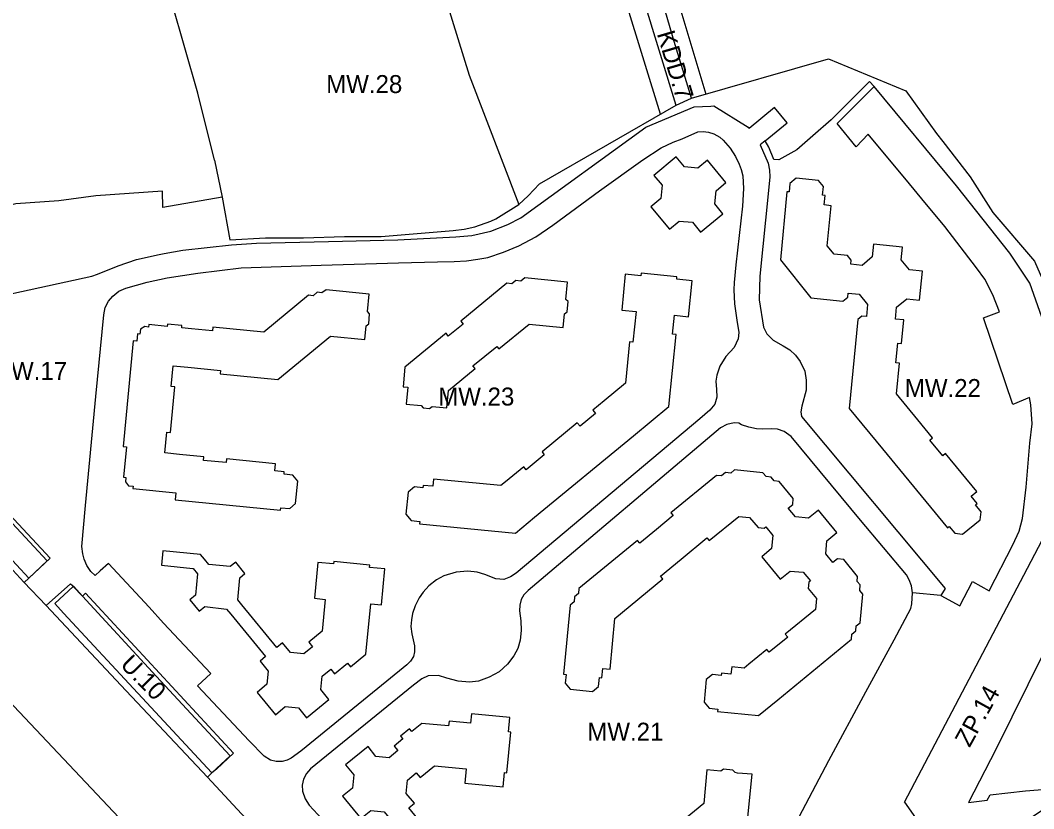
# Model space of a CAD drawing. Extents: x 7426178 to 7427732, y 5548847 to 5550287.
# Drawn here: x 7426699.7 to 7426953.6, y 5549707.1 to 5549904.6 of the extents above; entities that cross this region are included whole.
import ezdxf

# ---------------------------------------------------------------- set-up
doc = ezdxf.new("R2010")
doc.units = 0
for name, color, linetype in [('linie_rozgraniczajace', 7, 'Continuous'), ('linie_zabudowy_nieprzekraczalne', 7, 'Continuous'), ('linie_zabudowy_obowiazujace', 7, 'Continuous'), ('oznaczenia_przeznaczen', 7, 'Continuous')]:
    doc.layers.add(name, color=color, linetype=linetype)

msp = doc.modelspace()

# ---------------------------------------------------------------- linework, layer by layer
at = {"layer": 'linie_rozgraniczajace'}
for p, q in [((7426867.89, 5549885.09), (7426902.2, 5549894.9)), ((7426886.29, 5549874.39), (7426885.09, 5549873.37)), ((7426748.35, 5549869.5), (7426750.28, 5549860.25)), ((7426794.47, 5549843.8), (7426804.23, 5549844.06)), ((7426700.65, 5549763.84), (7426700.65, 5549763.84)), ((7426706.19, 5549757.95), (7426700.65, 5549763.84)), ((7426930.31, 5549760.48), (7426923.22, 5549761.13))]:
    msp.add_line(p, q, dxfattribs=at)
for points in [[(7426376.27, 5550136.98), (7426418.26, 5550074.28), (7426423.32, 5550066.18), (7426432.5, 5550051.32), (7426442.7, 5550038.38), (7426480.49, 5549982.45), (7426537.39, 5549902.3), (7426546.67, 5549891.59), (7426553.32, 5549883.92), (7426562.25, 5549871.78), (7426591.41, 5549843), (7426644.02, 5549790.07), (7426768.78, 5549657.84), (7426806.41, 5549611.72)], [(7426832.18, 5549989.03), (7426839.49, 5549964.6), (7426845.83, 5549943.49), (7426851.15, 5549925.23), (7426855.77, 5549910), (7426863.95, 5549883.29)], [(7426790.09, 5549942.81), (7426797.59, 5549944.63), (7426799.94, 5549929.65), (7426806.51, 5549909.21), (7426812.16, 5549890.84), (7426824.57, 5549858.44)], [(7426748.35, 5549869.5), (7426744.18, 5549886.34), (7426737.69, 5549909.01), (7426736.68, 5549911.95), (7426722.25, 5549906.56), (7426716.61, 5549921.27)], [(7426867.89, 5549885.09), (7426863.5, 5549899.25), (7426859.57, 5549912.74)], [(7426902.2, 5549894.9), (7426921.51, 5549886.93)], [(7426913.6, 5549887.98), (7426912.46, 5549889.24), (7426902.87, 5549879.62), (7426898.28, 5549875.63), (7426894.22, 5549872.08), (7426889.75, 5549869.63), (7426888.43, 5549869.71), (7426887.24, 5549872.76), (7426886.29, 5549874.39), (7426891.83, 5549878.89), (7426888.65, 5549882.71), (7426882.29, 5549877.48)], [(7426885.09, 5549873.37), (7426887.08, 5549868.75), (7426887.37, 5549867.04), (7426887.43, 5549865.33), (7426887.16, 5549861.94), (7426884.93, 5549840.48), (7426884.78, 5549834.57), (7426885.92, 5549827.69), (7426886.73, 5549826.02), (7426888.32, 5549824.44), (7426890.85, 5549823.06), (7426892.47, 5549822.01), (7426893.88, 5549820.67), (7426895.05, 5549819.06), (7426896.22, 5549816.67), (7426896.56, 5549814.46), (7426896.55, 5549811.95), (7426895.49, 5549807.9), (7426895.21, 5549806.51), (7426895.43, 5549805.3), (7426931.35, 5549762.2), (7426930.31, 5549760.48), (7426935.02, 5549757.91), (7426938.23, 5549763.99), (7426942.44, 5549761.68), (7426948.32, 5549773.17), (7426949.91, 5549776.58), (7426950.73, 5549779.76), (7426951.69, 5549787.64), (7426952.58, 5549798.68), (7426953.14, 5549803.51), (7426952.83, 5549808.21), (7426952.48, 5549810.07), (7426948.34, 5549808.36), (7426940.95, 5549830.03), (7426945.03, 5549831.5), (7426943.34, 5549835.78), (7426941.36, 5549839.75), (7426939.25, 5549842.52), (7426931.29, 5549852.9), (7426925.53, 5549859.82), (7426922.44, 5549863.63), (7426912.09, 5549876.06), (7426909.06, 5549872.85), (7426904.34, 5549878.68), (7426913.6, 5549887.98)], [(7426921.19, 5549708.68), (7426951.11, 5549765.58), (7426956.6, 5549776.07), (7426959.16, 5549797.97), (7426961.99, 5549798.27), (7426962.58, 5549807), (7426960.6, 5549815.99), (7426952.6, 5549838.71), (7426947.62, 5549846.2), (7426934.23, 5549863.11), (7426913.6, 5549887.98)], [(7426824.57, 5549858.44), (7426826.91, 5549860.63), (7426829.76, 5549863.61), (7426864.02, 5549883.33), (7426867.89, 5549885.09)], [(7426921.51, 5549886.93), (7426929.22, 5549876.25), (7426930.78, 5549874.24), (7426937.63, 5549865.37), (7426943.32, 5549856.38), (7426953.79, 5549844.23), (7426959.19, 5549831.83), (7426963.61, 5549821.24), (7426965.71, 5549809.49), (7426966.05, 5549784.81), (7426964.49, 5549773.85), (7426962.7, 5549765.31), (7426980.6, 5549768.08), (7426985.31, 5549769.35)], [(7426735.78, 5549846.15), (7426740.47, 5549846.99), (7426752.63, 5549848.35), (7426758.87, 5549848.74), (7426776.96, 5549849.18), (7426794.32, 5549849.61), (7426808.86, 5549850.31), (7426812.83, 5549850.66), (7426817.56, 5549851.74), (7426821.87, 5549853.43), (7426825.07, 5549855.05), (7426856.4, 5549877.8), (7426868.55, 5549882.89), (7426872.7, 5549883.08)], [(7426872.7, 5549883.08), (7426873.48, 5549883.12), (7426882.06, 5549877.83), (7426882.29, 5549877.48)], [(7426855.62, 5549869.6), (7426860.24, 5549872.59), (7426863.25, 5549874.07), (7426865.49, 5549874.87), (7426869.42, 5549876.62), (7426870.76, 5549876.69), (7426872.09, 5549876.51), (7426873.46, 5549876.16), (7426874.91, 5549875.26), (7426875.78, 5549874.55), (7426877.51, 5549872.54), (7426878.87, 5549870.41), (7426879.82, 5549868.55), (7426880.32, 5549867.19)], [(7426828.88, 5549850.34), (7426833.1, 5549853.24), (7426844.78, 5549861.82), (7426855.62, 5549869.6)], [(7426880.32, 5549867.19), (7426880.73, 5549865.64), (7426880.87, 5549862.43), (7426880.63, 5549858.02), (7426878.97, 5549843.29), (7426878.54, 5549838.85), (7426878.47, 5549837.06)], [(7426750.28, 5549860.25), (7426735.44, 5549857.68), (7426735.34, 5549861.78), (7426718.63, 5549860.57), (7426709.36, 5549859.35), (7426698.65, 5549858.57), (7426685.11, 5549855.15), (7426672.58, 5549851.69), (7426632.66, 5549838.16)], [(7426750.28, 5549860.25), (7426752.23, 5549849.57), (7426761.14, 5549850.09), (7426770.65, 5549850.06), (7426780.93, 5549850.37), (7426790.15, 5549850.41), (7426808.15, 5549851.95), (7426810.9, 5549852.24), (7426813.62, 5549852.86), (7426817.58, 5549854.29), (7426818.86, 5549854.84), (7426824.57, 5549858.44)], [(7426816.83, 5549845.12), (7426820.73, 5549846.46), (7426824.57, 5549848.08), (7426828.88, 5549850.34)], [(7426644.29, 5549825.35), (7426656.53, 5549812.26), (7426666.12, 5549802), (7426671.29, 5549806.84), (7426667.68, 5549810.5), (7426669.3, 5549829.97), (7426717.68, 5549840.5), (7426719.08, 5549840.97), (7426724.23, 5549843.09), (7426728.86, 5549844.63), (7426734.53, 5549845.92), (7426735.78, 5549846.15)], [(7426720.63, 5549830.76), (7426721.02, 5549832.59), (7426721.79, 5549834.21), (7426722.9, 5549835.49), (7426724.41, 5549836.7), (7426726.15, 5549837.47), (7426731.5, 5549838.99), (7426736.49, 5549840.05), (7426744.18, 5549841.23), (7426755.05, 5549842.6), (7426775.11, 5549843.2), (7426794.47, 5549843.8)], [(7426804.23, 5549844.06), (7426808.44, 5549844.17), (7426811.48, 5549844.3), (7426814.37, 5549844.7), (7426816.83, 5549845.12)], [(7426878.47, 5549837.06), (7426878.63, 5549833.52), (7426879.2, 5549829.47), (7426879.72, 5549826.34), (7426879.56, 5549824.81), (7426878.53, 5549822.59), (7426876.42, 5549820.38), (7426874.92, 5549817.91), (7426874.22, 5549815.71), (7426873.93, 5549814.16), (7426874.14, 5549812.07), (7426874.16, 5549810.16), (7426873.69, 5549808.44), (7426872.46, 5549806.87), (7426869.93, 5549804.73), (7426823.97, 5549766.11), (7426822.55, 5549765.15), (7426820.81, 5549764.53), (7426818.88, 5549764.63), (7426816.07, 5549765.74), (7426814.18, 5549766.3), (7426811.79, 5549766.57), (7426808.94, 5549766.36), (7426805.85, 5549765.43), (7426803.94, 5549764.41), (7426802.06, 5549762.94), (7426800.6, 5549761.31), (7426799.62, 5549759.92), (7426798.66, 5549757.86), (7426798, 5549755.96), (7426797.74, 5549754.41), (7426797.55, 5549752.76), (7426797.79, 5549750.89), (7426798.47, 5549747.91), (7426798.49, 5549746.35), (7426798.18, 5549745.24), (7426797.47, 5549744), (7426796.57, 5549743.11), (7426791.57, 5549739.05), (7426769.99, 5549721.48), (7426767.59, 5549719.76), (7426766.54, 5549719.23), (7426765.36, 5549718.94), (7426763.82, 5549718.93), (7426762.37, 5549719.28), (7426760.83, 5549720.2), (7426757.03, 5549724.12), (7426744.14, 5549737.88)], [(7426718.47, 5549765.47), (7426717.37, 5549766.48), (7426716.41, 5549767.96), (7426715.7, 5549769.61), (7426715.37, 5549770.94), (7426715.12, 5549772.73), (7426716.1, 5549783.07), (7426718.66, 5549810.36), (7426720.63, 5549830.76)], [(7426671.29, 5549806.84), (7426672.03, 5549807.52), (7426707.23, 5549769.84), (7426701.88, 5549764.81), (7426700.72, 5549763.76), (7426700.65, 5549763.84), (7426688.57, 5549776.82), (7426666.12, 5549802)], [(7426893.27, 5549702.02), (7426902.25, 5549719.14), (7426911.55, 5549736.38), (7426918.58, 5549749.41), (7426922.77, 5549757.19), (7426923.06, 5549758.37), (7426923.22, 5549761.13), (7426922.94, 5549762.89), (7426922.41, 5549764.43), (7426921.68, 5549765.63), (7426910.19, 5549779.38), (7426892.82, 5549800.3), (7426891.03, 5549801.54), (7426889.37, 5549802.15), (7426887.85, 5549802.27), (7426885.67, 5549802.16), (7426884.13, 5549802.22), (7426882.22, 5549802.63), (7426880.37, 5549803.27), (7426879.72, 5549803.64), (7426878.53, 5549803.71), (7426876.72, 5549803.35), (7426875.12, 5549802.5), (7426826.9, 5549761.75), (7426825.88, 5549760.63), (7426825.17, 5549759.46), (7426824.84, 5549758.04), (7426824.8, 5549756.63), (7426825.08, 5549754.14), (7426825.18, 5549751.73), (7426824.93, 5549749.3), (7426824.34, 5549747.23), (7426823.37, 5549745.39), (7426821.72, 5549743.32), (7426819.65, 5549741.39), (7426817.16, 5549740.01), (7426814.49, 5549739.06), (7426812.21, 5549738.81), (7426809.39, 5549739.05), (7426806.54, 5549739.74), (7426804.45, 5549740.45), (7426801.93, 5549740.38), (7426800.31, 5549739.64), (7426798.21, 5549738.03), (7426772.44, 5549717.11), (7426771.4, 5549715.92), (7426770.7, 5549714.46), (7426770.35, 5549713), (7426770.4, 5549711.46), (7426771.05, 5549709.57), (7426772.11, 5549707.95), (7426785.12, 5549693.98)], [(7426735.6, 5549753.59), (7426732.04, 5549757.54), (7426721.78, 5549768.52), (7426719.73, 5549766.67), (7426718.47, 5549765.47)], [(7426960.1, 5549754.29), (7426944.05, 5549721.95), (7426937.2, 5549708.62), (7426941.9, 5549709.19), (7426942.64, 5549710.57), (7426951.51, 5549711.54), (7426958.87, 5549712.14), (7426996.53, 5549715.51), (7427002.21, 5549716.59), (7427004.76, 5549717.21), (7427010.19, 5549718.81), (7427041.49, 5549731.55), (7427083.98, 5549748.53), (7427093.57, 5549752.35), (7427093.82, 5549751.76), (7427128.13, 5549765.67)], [(7426706.19, 5549757.95), (7426712.33, 5549763.43), (7426713.11, 5549762.75), (7426715.35, 5549760.32), (7426716.05, 5549761.09), (7426753.15, 5549720.96), (7426748.85, 5549716.98), (7426747.71, 5549716.05), (7426746.58, 5549715.01)], [(7426810.33, 5549646.2), (7426800.44, 5549656.88), (7426791.22, 5549666.83), (7426763.7, 5549696.53), (7426746.59, 5549715), (7426724.9, 5549738.06), (7426706.19, 5549757.95)], [(7426744.14, 5549737.88), (7426747.48, 5549740.97), (7426735.6, 5549753.59)], [(7426921.19, 5549708.68), (7426923.92, 5549704.82), (7426932.51, 5549700.17), (7426935.18, 5549699.15), (7426937.7, 5549698.72), (7426940.53, 5549698.67), (7426942.25, 5549698.99), (7426944.97, 5549699.87), (7426946.33, 5549700.48), (7426947.4, 5549701.24), (7426955.49, 5549706.64), (7426958.19, 5549707.88), (7426961.05, 5549708.75), (7426963.27, 5549709.23), (7426965.77, 5549709.6), (7426974.88, 5549710.13), (7426996.27, 5549711.61), (7427000.22, 5549712.16), (7427006.34, 5549713.7), (7427091.63, 5549747.86), (7427113.84, 5549707.59), (7427113.65, 5549702.41), (7427125.67, 5549680.75), (7427127, 5549680.04)]]:
    msp.add_lwpolyline(points, dxfattribs=at)
at = {"layer": 'linie_zabudowy_nieprzekraczalne'}
for points in [[(7426841.67, 5549986.58), (7426844.99, 5549972.04), (7426847.36, 5549962.92), (7426861.89, 5549913.58), (7426863.14, 5549913.73), (7426871.44, 5549886.1)], [(7426860.08, 5549881.06), (7426851.6, 5549908.72), (7426845.76, 5549928.77), (7426840.38, 5549945.88), (7426841.93, 5549946.37), (7426837.76, 5549959.78), (7426836.17, 5549959.27), (7426828.36, 5549984.13)]]:
    msp.add_lwpolyline(points, dxfattribs=at)
at = {"layer": 'linie_zabudowy_obowiazujace'}
for p, q in [((7426907.09, 5549836.24), (7426909.86, 5549835.97)), ((7426911.69, 5549830.39), (7426910.51, 5549830.49)), ((7426828.56, 5549780.07), (7426853.3, 5549800.45)), ((7426738.66, 5549786.22), (7426738.49, 5549784.43)), ((7426859.11, 5549777.05), (7426854.93, 5549773.61)), ((7426865.25, 5549769.6), (7426871.72, 5549774.91)), ((7426745.86, 5549769.55), (7426744.84, 5549770.79)), ((7426715.35, 5549760.32), (7426713.01, 5549762.7)), ((7426897.64, 5549764.14), (7426897.21, 5549763.79)), ((7426733.77, 5549740.29), (7426715.35, 5549760.32)), ((7426755.25, 5549758.13), (7426754.18, 5549759.43)), ((7426764, 5549747.5), (7426755.25, 5549758.13)), ((7426710.58, 5549756.03), (7426729.19, 5549736.04)), ((7426752.43, 5549755.8), (7426761.18, 5549745.18)), ((7426882.21, 5549743.25), (7426881.05, 5549742.27)), ((7426805.86, 5549696.65), (7426797.05, 5549707.34))]:
    msp.add_line(p, q, dxfattribs=at)
for points in [[(7426876.49, 5549863.93), (7426871.87, 5549869.52), (7426869.41, 5549867.49), (7426866.11, 5549867.84), (7426864, 5549870.34), (7426858.45, 5549865.67), (7426860.48, 5549863.26), (7426860.16, 5549859.89), (7426857.69, 5549857.85), (7426862.31, 5549852.25), (7426864.77, 5549854.28), (7426868.08, 5549853.96), (7426870.12, 5549851.49), (7426875.72, 5549856.11), (7426873.69, 5549858.57), (7426874.02, 5549861.88), (7426876.49, 5549863.93)], [(7426907.78, 5549843.45), (7426907.87, 5549844.51), (7426906.93, 5549845.63), (7426903.61, 5549845.96), (7426901.87, 5549848.06), (7426902.86, 5549858.12), (7426901.06, 5549858.3), (7426901.3, 5549860.69), (7426900.69, 5549860.75), (7426900.9, 5549862.92), (7426899.64, 5549864.46), (7426894.06, 5549865), (7426892.48, 5549863.68), (7426892.28, 5549861.57), (7426891.69, 5549861.63), (7426890.12, 5549844.57), (7426897.77, 5549835.03), (7426905.77, 5549834.22), (7426906.99, 5549835.24), (7426907.09, 5549836.24)], [(7426918.91, 5549829.72), (7426919.19, 5549832.69), (7426921.77, 5549834.81), (7426924.95, 5549834.49), (7426925.68, 5549841.71), (7426922.47, 5549842.04), (7426920.35, 5549844.59), (7426920.66, 5549847.77), (7426913.45, 5549848.48), (7426913.14, 5549845.31), (7426910.56, 5549843.18), (7426907.78, 5549843.45)], [(7426836.82, 5549839), (7426826.1, 5549840.02), (7426825.13, 5549839.24), (7426823.86, 5549839.36), (7426822.87, 5549838.56), (7426821.61, 5549838.68), (7426810.05, 5549829.19), (7426810.63, 5549828.49), (7426806.94, 5549825.46), (7426806.37, 5549826.16), (7426796.07, 5549817.7), (7426795.6, 5549812.76), (7426796.77, 5549812.65), (7426796.38, 5549808.44), (7426800.13, 5549808.09), (7426800.63, 5549807.48), (7426802.22, 5549807.3), (7426802.89, 5549807.84), (7426806.6, 5549807.48), (7426807, 5549811.86), (7426813.68, 5549817.31), (7426813.11, 5549818.01), (7426819.08, 5549822.89), (7426819.62, 5549822.23), (7426827.19, 5549828.41), (7426835.71, 5549827.61), (7426836.05, 5549831.05), (7426836.73, 5549831.58), (7426836.95, 5549834.09), (7426836.4, 5549834.66), (7426836.82, 5549839)], [(7426853.3, 5549800.45), (7426862.2, 5549807.81), (7426864, 5549825.87), (7426863.1, 5549825.96), (7426863.56, 5549830.67), (7426867.13, 5549830.31), (7426868.03, 5549839.32), (7426864.14, 5549839.71), (7426864.2, 5549840.29), (7426855.2, 5549841.19), (7426855.13, 5549840.58), (7426851.27, 5549840.96), (7426850.37, 5549831.95), (7426853.95, 5549831.6), (7426853.18, 5549823.9), (7426852.31, 5549823.99), (7426851.28, 5549813.65), (7426846, 5549809.28)], [(7426741.72, 5549817.67), (7426749.89, 5549816.87), (7426749.8, 5549815.98), (7426764.27, 5549814.57), (7426777.45, 5549825.42), (7426786, 5549824.59), (7426786.33, 5549828.03), (7426786.99, 5549828.53), (7426787.23, 5549831.04), (7426786.69, 5549831.65), (7426787.11, 5549835.99), (7426776.36, 5549837.04), (7426775.28, 5549836.27), (7426774.07, 5549836.43), (7426773.09, 5549835.57), (7426771.88, 5549835.68), (7426760.69, 5549826.43), (7426747.92, 5549827.68), (7426747.84, 5549826.78), (7426742.65, 5549827.29)], [(7426909.86, 5549835.97), (7426911.97, 5549833.38), (7426911.69, 5549830.39)], [(7426910.51, 5549830.49), (7426909.52, 5549829.66), (7426907.32, 5549807.36), (7426915.68, 5549797.21)], [(7426924.53, 5549804.5), (7426919.19, 5549810.98), (7426919.94, 5549818.66), (7426919.07, 5549818.75), (7426919.56, 5549823.73), (7426920.43, 5549823.64), (7426921.01, 5549829.51), (7426918.91, 5549829.72)], [(7426742.65, 5549827.29), (7426740.16, 5549827.53), (7426740.21, 5549828.13), (7426736.57, 5549828.48), (7426736.51, 5549827.88), (7426731.94, 5549828.33), (7426731.88, 5549827.73), (7426730.9, 5549827.83), (7426729.81, 5549827.17), (7426729.69, 5549825.94), (7426729.1, 5549825.99), (7426728.92, 5549824.2), (7426728.03, 5549824.29), (7426725.46, 5549797.78), (7426726.34, 5549797.7), (7426725.61, 5549790.1), (7426726.2, 5549790.05), (7426726.1, 5549788.92), (7426726.84, 5549787.98), (7426728, 5549787.86), (7426727.94, 5549787.27), (7426738.66, 5549786.22)], [(7426739.6, 5549795.84), (7426735.9, 5549796.2), (7426736.41, 5549801.41), (7426737.31, 5549801.32), (7426738.42, 5549812.73), (7426737.52, 5549812.82), (7426738.03, 5549818.02), (7426741.72, 5549817.67)], [(7426846, 5549809.28), (7426843.15, 5549806.92), (7426843.82, 5549806.11), (7426839.94, 5549802.9), (7426839.25, 5549803.73), (7426830.42, 5549796.43), (7426830.98, 5549795.76), (7426826.4, 5549791.97), (7426825.82, 5549792.68), (7426821.26, 5549788.95)], [(7426915.68, 5549797.21), (7426932, 5549777.4), (7426932.43, 5549777.75), (7426933.79, 5549776.08), (7426935.77, 5549775.86), (7426940.14, 5549779.48), (7426940.37, 5549781.47), (7426938.97, 5549783.17), (7426939.42, 5549783.54), (7426937.91, 5549785.37), (7426939.3, 5549786.52), (7426931.44, 5549796.05), (7426930.77, 5549795.5), (7426927.55, 5549799.39), (7426928.24, 5549799.97), (7426924.53, 5549804.5)], [(7426738.49, 5549784.43), (7426764.93, 5549781.9), (7426764.98, 5549782.46), (7426767.2, 5549782.25), (7426768.7, 5549783.53), (7426769.25, 5549789.14), (7426767.99, 5549790.66), (7426765.8, 5549790.88), (7426765.86, 5549791.47), (7426763.47, 5549791.71), (7426763.64, 5549793.5), (7426751.34, 5549794.69), (7426751.26, 5549793.8), (7426745.64, 5549794.34), (7426745.73, 5549795.24), (7426739.6, 5549795.84)], [(7426892.1, 5549782.33), (7426893.2, 5549783.26), (7426893.35, 5549784.81), (7426889.83, 5549789.04), (7426888.58, 5549789.18), (7426887.78, 5549790.15), (7426886.51, 5549790.29), (7426885.74, 5549791.25), (7426878.61, 5549791.94), (7426877.66, 5549791.14), (7426876.4, 5549791.3), (7426875.35, 5549790.45), (7426874.13, 5549790.58), (7426862.71, 5549781.16), (7426863.27, 5549780.49), (7426859.11, 5549777.05)], [(7426683.24, 5549784.83), (7426701.88, 5549764.81), (7426706.5, 5549769.16), (7426687.82, 5549789.1)], [(7426821.26, 5549788.95), (7426820.13, 5549788), (7426803.22, 5549789.65), (7426803.06, 5549787.87), (7426800.64, 5549788.08), (7426800.59, 5549787.49), (7426798.49, 5549787.68), (7426796.89, 5549786.37), (7426796.32, 5549780.9), (7426797.65, 5549779.24), (7426799.77, 5549779.03), (7426799.71, 5549778.45), (7426823.8, 5549776.06), (7426828.56, 5549780.07)], [(7426903.25, 5549768.75), (7426901.46, 5549770.91), (7426901.78, 5549774.22), (7426904.26, 5549776.26), (7426899.63, 5549781.86), (7426897.17, 5549779.84), (7426893.86, 5549780.16), (7426892.1, 5549782.33)], [(7426871.72, 5549774.91), (7426872.28, 5549774.23), (7426879.7, 5549780.31), (7426882.4, 5549780.05), (7426884.58, 5549777.5), (7426886.06, 5549777.35), (7426886.46, 5549777.7)], [(7426886.46, 5549777.7), (7426888.24, 5549775.54), (7426887.92, 5549772.23), (7426885.46, 5549770.21), (7426890.07, 5549764.58), (7426892.53, 5549766.61), (7426895.85, 5549766.31), (7426897.64, 5549764.14)], [(7426854.93, 5549773.61), (7426854.35, 5549774.3), (7426839.67, 5549762.21), (7426839.56, 5549760.98), (7426838.58, 5549760.16), (7426838.48, 5549758.88), (7426837.49, 5549758.1), (7426835.79, 5549740.77), (7426836.42, 5549740.7), (7426836.19, 5549738.56), (7426837.47, 5549736.99), (7426843.02, 5549736.48), (7426844.59, 5549737.73), (7426844.8, 5549739.91), (7426845.39, 5549739.85), (7426845.62, 5549742.23), (7426847.44, 5549742.05), (7426848.67, 5549754.76), (7426860.7, 5549764.68), (7426860.12, 5549765.37), (7426865.25, 5549769.6)], [(7426744.84, 5549770.79), (7426735.42, 5549771.7), (7426735.07, 5549768.06), (7426742.98, 5549767.29), (7426743.04, 5549767.22)], [(7426754.18, 5549759.43), (7426754.72, 5549764.95), (7426756.01, 5549766.02), (7426753.69, 5549768.84), (7426752.3, 5549767.71), (7426746.95, 5549768.23), (7426745.86, 5549769.55)], [(7426777.51, 5549742.05), (7426778.46, 5549740.89), (7426781.7, 5549743.56), (7426782.46, 5549742.63), (7426786.27, 5549745.76), (7426787.5, 5549758.41), (7426790.19, 5549758.15), (7426791.06, 5549767.15), (7426787.18, 5549767.52), (7426787.24, 5549768.12), (7426778.24, 5549768.99), (7426778.18, 5549768.4), (7426774.25, 5549768.78), (7426773.39, 5549759.79), (7426776.11, 5549759.52), (7426775.35, 5549751.58), (7426771.96, 5549748.8), (7426772.91, 5549747.64)], [(7426889.49, 5549734.39), (7426907.89, 5549749.51), (7426908.02, 5549750.81), (7426908.99, 5549751.6), (7426909.09, 5549752.87), (7426910.07, 5549753.64), (7426910.77, 5549760.79), (7426910.01, 5549761.72), (7426910.1, 5549763.14), (7426909.32, 5549764.02), (7426909.42, 5549765.27), (7426905.97, 5549769.49), (7426904.42, 5549769.69), (7426903.25, 5549768.75)], [(7426743.04, 5549767.22), (7426744.12, 5549765.9), (7426743.6, 5549760.55), (7426742.21, 5549759.4), (7426744.55, 5549756.58), (7426745.92, 5549757.72), (7426751.35, 5549757.1), (7426752.43, 5549755.8)], [(7426713.01, 5549762.7), (7426708.42, 5549758.45), (7426710.58, 5549756.03)], [(7426897.21, 5549763.79), (7426897.06, 5549762.24), (7426899.15, 5549759.7), (7426898.89, 5549756.97), (7426891.35, 5549750.77), (7426891.94, 5549750.06), (7426887.34, 5549746.27), (7426886.75, 5549746.99), (7426882.21, 5549743.25)], [(7426772.91, 5549747.64), (7426770.73, 5549745.85), (7426767.41, 5549746.17), (7426765.39, 5549748.64), (7426764, 5549747.5)], [(7426761.18, 5549745.18), (7426759.8, 5549744.03), (7426761.82, 5549741.57), (7426761.5, 5549738.25), (7426759.04, 5549736.22), (7426763.63, 5549730.63), (7426766.09, 5549732.66), (7426769.42, 5549732.34), (7426771.45, 5549729.85), (7426777.03, 5549734.47), (7426775.01, 5549736.93), (7426775.33, 5549740.26), (7426777.51, 5549742.05)], [(7426881.05, 5549742.27), (7426877.91, 5549742.6), (7426877.72, 5549740.8), (7426875.33, 5549741.05), (7426875.27, 5549740.45), (7426873.07, 5549740.68), (7426871.56, 5549739.44), (7426870.99, 5549733.75), (7426872.26, 5549732.26), (7426874.45, 5549732.03), (7426874.39, 5549731.44), (7426884.67, 5549730.45), (7426889.49, 5549734.39)], [(7426729.19, 5549736.04), (7426747.71, 5549716.05), (7426752.29, 5549720.32), (7426733.77, 5549740.29)], [(7426798.92, 5549716.04), (7426799.87, 5549714.88), (7426803.49, 5549717.86), (7426811.4, 5549717.09), (7426811.06, 5549713.5), (7426820.65, 5549712.57), (7426821, 5549716.15), (7426821.59, 5549716.09), (7426822.58, 5549726.28), (7426821.99, 5549726.34), (7426822.33, 5549729.92), (7426812.74, 5549730.85), (7426812.51, 5549728.47), (7426807.13, 5549728.99), (7426807.02, 5549727.8), (7426800.27, 5549728.45), (7426797.8, 5549726.42), (7426797.23, 5549727.12), (7426794.96, 5549725.25), (7426795.53, 5549724.56), (7426793.37, 5549722.78), (7426794.32, 5549721.62)], [(7426794.32, 5549721.62), (7426792.15, 5549719.83), (7426788.82, 5549720.15), (7426786.82, 5549722.64), (7426781.2, 5549718.03), (7426783.23, 5549715.55), (7426782.9, 5549712.24), (7426780.44, 5549710.21), (7426785.04, 5549704.65), (7426787.5, 5549706.64), (7426790.83, 5549706.33), (7426792.86, 5549703.86), (7426794.22, 5549704.99)], [(7426881.75, 5549702.44), (7426883.04, 5549715.7), (7426879.36, 5549716.02), (7426878.78, 5549716.13), (7426878.24, 5549716.77), (7426875.83, 5549717.01), (7426875.18, 5549716.49), (7426871.66, 5549716.81), (7426870.9, 5549708.36), (7426865.34, 5549703.76)], [(7426797.05, 5549707.34), (7426798.45, 5549708.46), (7426796.42, 5549710.93), (7426796.74, 5549714.25), (7426798.92, 5549716.04)]]:
    msp.add_lwpolyline(points, dxfattribs=at)

# ---------------------------------------------------------------- texts
at = {"layer": 'oznaczenia_przeznaczen'}
for s, rotation, p in [('KDD.7', 286.4682, (7426859.14, 5549901.23)), ('U.10', 314.5327, (7426724.53, 5549742.94)), ('ZP.14', 61.1414, (7426937.51, 5549722.23))]:
    msp.add_text(s, height=4.5, rotation=rotation, dxfattribs=at).set_placement(p)
for s, p in [('MW.28', (7426776.35, 5549886.34)), ('KDW.17', (7426689.04, 5549814.48)), ('MW.22', (7426921.29, 5549810.2)), ('MW.23', (7426804.41, 5549808.07)), ('MW.21', (7426841.75, 5549724.12))]:
    msp.add_text(s, height=4.5, dxfattribs=at).set_placement(p)

doc.saveas('drawing.dxf')
